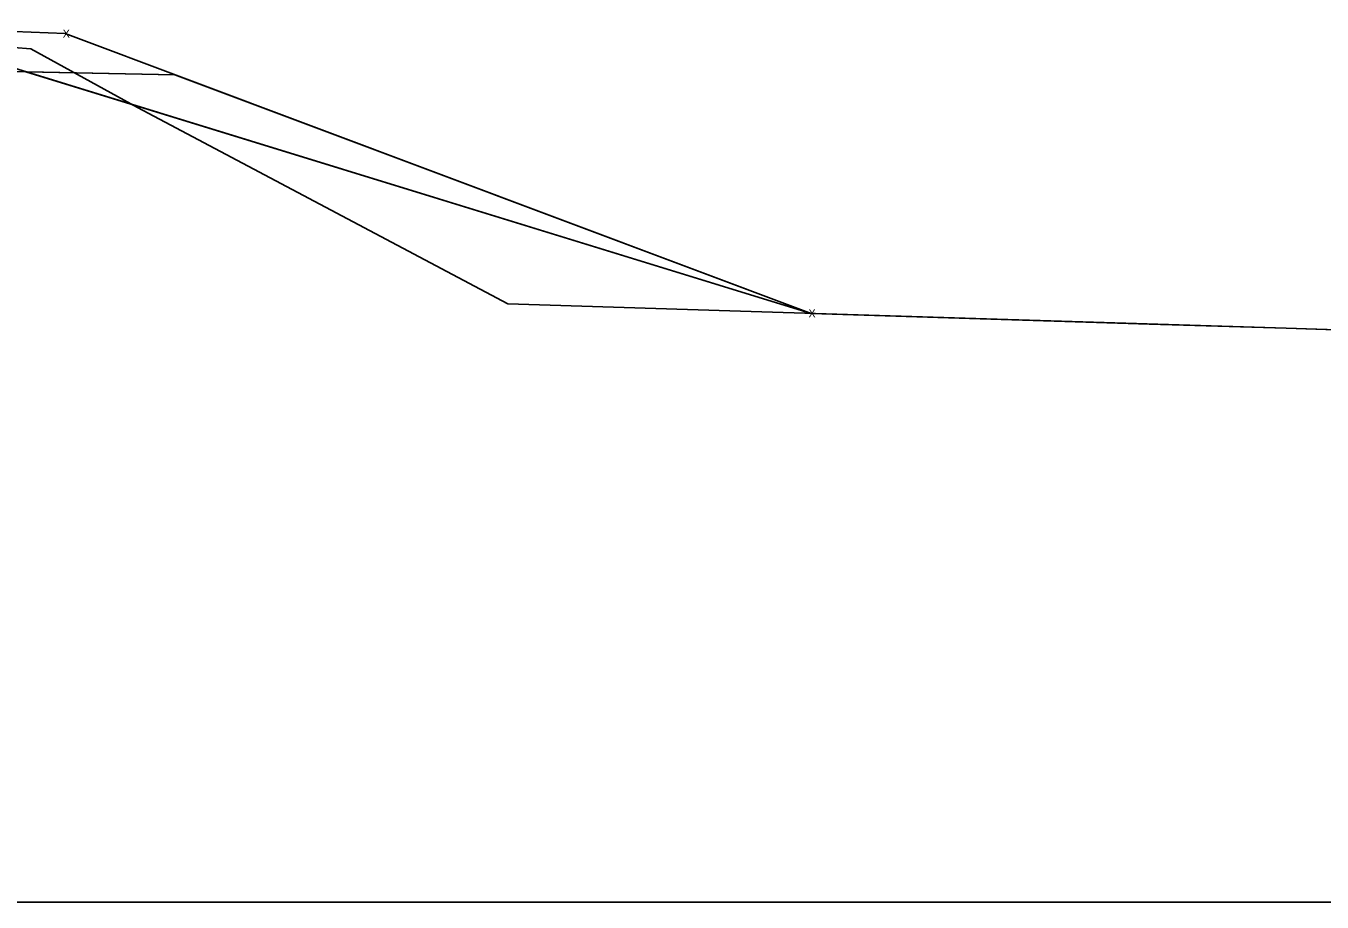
# Model space of a CAD drawing. Extents: x -26 to 303, y -16 to 6048.
# Drawn here: x 166.09 to 204.75, y 1500 to 1526.12 of the extents above; entities that cross this region are included whole.
import ezdxf

# ---------------------------------------------------------------- set-up
doc = ezdxf.new("R2010")
doc.units = 0
for name, color, linetype in [('DTM_P_FINISHED_GRADE2', 7, 'Continuous'), ('DTM_TEMP_DROP', 7, 'Continuous'), ('DTM_X_GROUND', 7, 'Continuous'), ('XS_CELL', 7, 'Continuous'), ('XS_M_SHAPES_EARTHWORK', 7, 'Continuous'), ('XS_P_GROUND', 7, 'Continuous'), ('XS_P_SHOULDER', 7, 'Continuous'), ('XS_P_SUBGRADE_GRANULAR', 7, 'Continuous')]:
    doc.layers.add(name, color=color, linetype=linetype)

msp = doc.modelspace()

# ---------------------------------------------------------------- linework, layer by layer
at = {"layer": 'DTM_P_FINISHED_GRADE2'}
msp.add_lwpolyline([(110.015, 1516.422), (110.015, 1516.422), (117.952, 1519.364), (126.406, 1522.502), (134.371, 1525.556), (138.871, 1525.736), (140.871, 1525.805), (150, 1526.124), (159.672, 1526.118), (161.672, 1526.116), (167.265, 1525.893), (189.507, 1517.552)], dxfattribs=at)
at = {"layer": 'DTM_X_GROUND'}
for points in [[(99.025, 1515.516), (110.015, 1516.422), (110.015, 1516.422), (110.015, 1516.422), (110.015, 1516.422), (129.467, 1522.625), (138.871, 1525.736), (138.871, 1525.736), (140.871, 1525.805), (140.871, 1525.805), (150, 1526.124), (150, 1526.124), (159.672, 1526.118), (159.672, 1526.118), (161.672, 1526.116), (189.507, 1517.552), (189.507, 1517.552), (189.507, 1517.552), (192.662, 1517.453), (199.593, 1517.236), (203.677, 1517.108), (205.443, 1517.052)], [(99.025, 1515.516), (113.066, 1516.674), (117.493, 1517.266), (133.178, 1523.176), (138.871, 1525.305), (142.418, 1525.452), (149.919, 1525.735), (158.682, 1525.77), (161.672, 1525.781), (163.69, 1525.637), (166.232, 1525.445), (169.417, 1523.693), (180.467, 1517.835), (187.086, 1517.627), (203.677, 1517.108), (211.013, 1516.878), (231.548, 1515.875), (274.675, 1515.807), (298.485, 1516.717), (300, 1516.718)]]:
    msp.add_lwpolyline(points, dxfattribs=at)
at = {"layer": 'XS_CELL'}
msp.add_line((150, 1500), (300, 1500), dxfattribs=at)
at = {"layer": 'XS_M_SHAPES_EARTHWORK'}
msp.add_lwpolyline([(166.09, 1524.757), (189.507, 1517.552), (170.529, 1524.668)], close=True, dxfattribs=at)
at = {"layer": 'XS_P_GROUND'}
msp.add_lwpolyline([(189.507, 1517.552), (189.507, 1517.552), (167.265, 1525.893)], dxfattribs=at)
at = {"layer": 'XS_P_SHOULDER'}
msp.add_lwpolyline([(161.672, 1526.116), (167.265, 1525.893)], dxfattribs=at)
at = {"layer": 'XS_P_SUBGRADE_GRANULAR'}
msp.add_lwpolyline([(161.672, 1524.845), (163.672, 1524.805), (170.529, 1524.668)], dxfattribs=at)

# ---------------------------------------------------------------- texts
at = {"layer": 'DTM_TEMP_DROP'}
msp.add_text('X', height=0.24, dxfattribs=at).set_placement((189.429, 1517.432))
at = {"layer": 'XS_P_GROUND'}
msp.add_text('X', height=0.24, dxfattribs=at).set_placement((167.186, 1525.773))
at = {"layer": 'XS_P_SUBGRADE_GRANULAR'}
msp.add_text('X', height=0.24, dxfattribs=at).set_placement((189.429, 1517.432))

doc.saveas('drawing.dxf')
